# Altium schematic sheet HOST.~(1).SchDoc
size A3; SheetNumber: 6; SheetTotal: 6
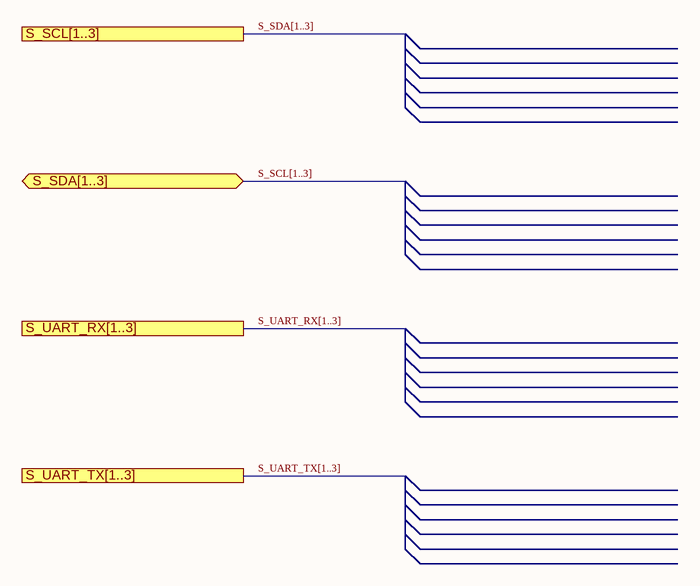
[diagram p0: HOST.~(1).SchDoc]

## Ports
S_SCL[1..3], S_SDA[1..3] (bidir), S_UART_RX[1..3], S_UART_TX[1..3]

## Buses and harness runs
bus S_SCL[1..3] = port S_SDA[1..3]
bus S_SDA[1..3] = port S_SCL[1..3]
bus S_UART_RX[1..3] = port S_UART_RX[1..3]
bus S_UART_TX[1..3] = port S_UART_TX[1..3]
